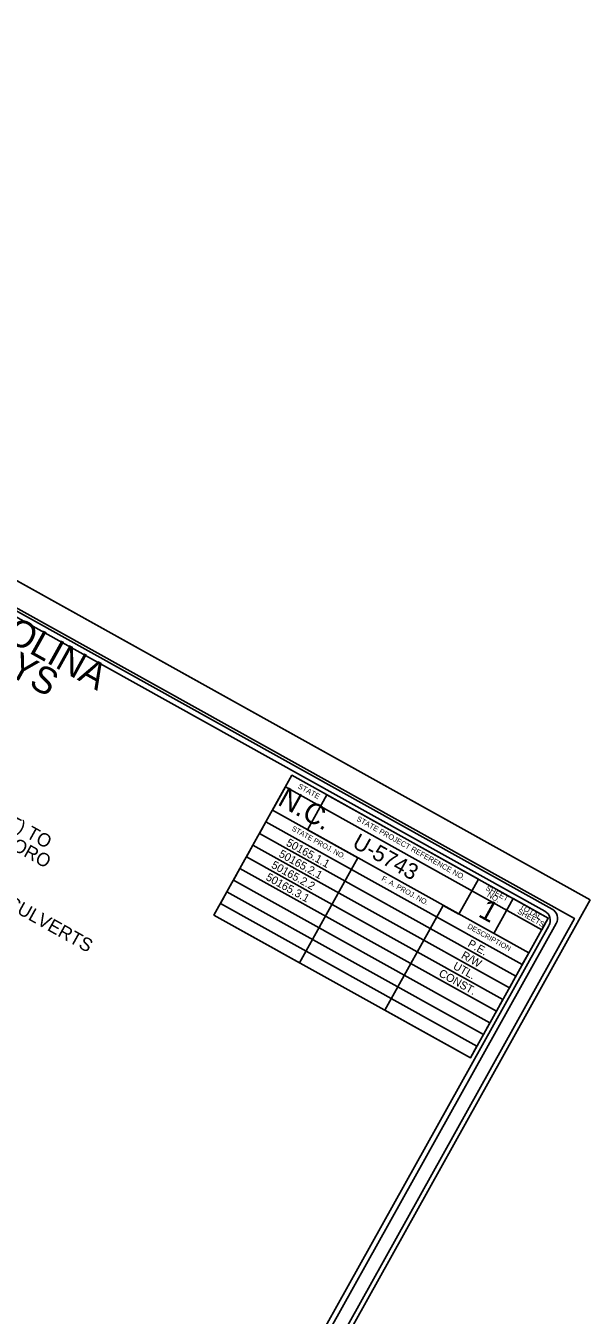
# Model space of a CAD drawing. Extents: x 1754939 to 1770240, y 706534 to 717510.
# Drawn here: x 1767067 to 1770240, y 710258 to 717510 of the extents above; entities that cross this region are included whole.
import ezdxf

# ---------------------------------------------------------------- set-up
doc = ezdxf.new("R2010")
doc.units = 0
for name, color, linetype in [('Culvert Barrel', 7, 'Continuous'), ('Culvert Wing', 7, 'Continuous'), ('Prop Conc Drive Radius Type', 7, 'Continuous'), ('Prop Lane Arrow CELL', 7, 'Continuous'), ('Scratch_Level_3', 7, 'Continuous')]:
    doc.layers.add(name, color=color, linetype=linetype)

msp = doc.modelspace()

# ---------------------------------------------------------------- linework, layer by layer
at = {"layer": 'Culvert Barrel'}
msp.add_line((1761412.2, 717510.1), (1770239.7, 712594.3), dxfattribs=at)
at = {"layer": 'Culvert Wing'}
msp.add_lwpolyline([(1770239.7, 712594.3), (1761412.2, 717510.1), (1758201.2, 711744), (1767028.7, 706828.1)], close=True, dxfattribs=at)
at = {"layer": 'Prop Conc Drive Radius Type'}
for points in [[(1770025.3, 712542), (1762267, 716862.5)], [(1769984.4, 712530.4), (1762540.8, 716675.6)], [(1768124.8, 712508.5), (1769566.3, 711705.7), (1769602.8, 711771.1), (1768161.3, 712574), (1768197.7, 712639.4), (1769639.3, 711836.7), (1769675.8, 711902.2), (1768234.3, 712704.9), (1768270.7, 712770.6), (1769712.3, 711967.8), (1769748.8, 712033.3), (1768307.2, 712836.1), (1768343.7, 712901.5), (1769785.3, 712098.8), (1769821.7, 712164.3), (1768380.2, 712967.1), (1768416.7, 713032.6), (1769858.2, 712229.8), (1769894.7, 712295.4), (1768453.2, 713098.2), (1768526.2, 713229.2), (1769967.7, 712426.5), (1770004.2, 712492), (1768562.6, 713294.7), (1768124.8, 712508.5), (1768605.2, 712240.8), (1768933.6, 712830.6), (1768649.7, 712988.6), (1768759.2, 713185.3), (1769611.1, 712710.8), (1769501.6, 712514.3), (1769414.1, 712563.1), (1769085.6, 711973.4), (1769566.3, 711705.7), (1770004.2, 712492), (1769807.6, 712601.5), (1769698.2, 712404.8)], [(1767041.7, 707061.2), (1770048.4, 712460.4)], [(1767570.1, 708071.7), (1770007.7, 712448.9)]]:
    msp.add_lwpolyline(points, dxfattribs=at)
for centre in [(1769955.4, 712478.3), (1769996.2, 712489.9)]:
    msp.add_arc(centre, 60, 330.88754, 60.88754, dxfattribs=at)
at = {"layer": 'Prop Lane Arrow CELL'}
msp.add_lwpolyline([(1758334.8, 711823.6), (1767070.6, 706958.9), (1770150.6, 712489.7), (1761414.8, 717354.5), (1758334.8, 711823.6)], dxfattribs=at)

# ---------------------------------------------------------------- texts
at = {"layer": 'Prop Conc Drive Radius Type'}
for s, height, p in [('STATE OF NORTH CAROLINA', 149.999, (1764996.4, 715146)), ('DIVISION OF HIGHWAYS', 149.999, (1765130.6, 714882.5)), ('STATE', 30, (1768593.8, 713224.2)), ('N.C.', 116.1, (1768477.1, 713131.9)), ('STATE PROJECT REFERENCE NO.', 29.999, (1768923.2, 713040.7)), ('STATE PROJ. NO.', 28.8, (1768559, 712986.7)), ('F. A. PROJ. NO.', 28.8, (1769063.8, 712705.6)), ('SHEET', 30, (1769649.7, 712651.5)), ('1', 116.1, (1769604.7, 712504)), ('NO.', 30, (1769657.1, 712613.5)), ('SHEETS', 30, (1769827.7, 712520.6)), ('TOTAL', 30, (1769840.6, 712547.7)), ('DESCRIPTION', 28.8, (1769546.6, 712436.7))]:
    msp.add_text(s, height=height, rotation=330.88754, dxfattribs=at).set_placement(p)
at = {"layer": 'Scratch_Level_3'}
for s, height, p in [('NC 42 FROM SR 2237 (EAST SALISBURY STREET) TO ', 75.001, (1764945.9, 714127.1)), ('NORTH OF US 64 / NC 49 (DIXIE DRIVE) IN ASHEBORO', 75.001, (1764898.1, 714041.2)), ('DRAINAGE, GRADING, PAVING, SIGNALS AND CULVERTS', 75.001, (1764991.8, 713646.3)), ('50165.1.1', 45, (1768526.5, 712902.4)), ('U-5743    ', 90, (1768896.1, 712893.2)), ('50165.2.1', 45, (1768485.3, 712839.5)), ('50165.2.2', 45, (1768443.2, 712777.2)), ('50165.3.1', 45, (1768412.4, 712708.6)), ('P.E.', 45, (1769547.2, 712334.7)), ('R/W', 45, (1769510.8, 712269.1)), ('UTL.', 45, (1769465.1, 712208.8)), ('CONST.', 45, (1769384.3, 712168))]:
    msp.add_text(s, height=height, rotation=330.88754, dxfattribs=at).set_placement(p)

doc.saveas('drawing.dxf')
